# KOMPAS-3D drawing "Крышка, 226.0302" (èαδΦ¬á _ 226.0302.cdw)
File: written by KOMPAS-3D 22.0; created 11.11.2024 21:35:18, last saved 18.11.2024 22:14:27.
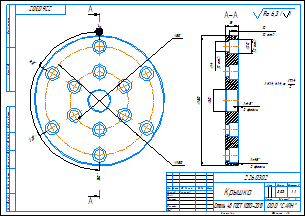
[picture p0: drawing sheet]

Sheet 1: A3, landscape

Document properties: Автор: aleksander.larionov.10@gmail.com; Знак неуказанной шероховатости: 4; Параметр неуказанной шероховатости: Ra 6,3; Полное имя файла: Крышка _ 226.0302.m3d; Масса: 3.032924

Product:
- Part/product: Крышка  | designation 226.0302
    Материал: Сталь 45 ГОСТ 1050-2013 (density 7810 kg/m3)
    Масса: 3.032924

Title block, sheet 1: Наименование: Крышка; designation: 226.0302; Материал: Сталь 45 ГОСТ 1050-2013; Масса: 3,03; Количество листов документа: 1; organisation: ООО "САЙН"; Форматы листов документа: A3; stored path: C:\Мои папки\Работа\Крышки, фланцы\226.0302\Крышка _ 226.0302.cdw; Разработал: Ларионов

Views: Вид 1, Сверху, Разрез А-А
Referenced files in C:\Мои папки\Работа\Крышки, фланцы\226.0302\: Крышка _ 226.0302.m3d
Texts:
  Ra 6,3
  Ra 6,3 ( )
Dimensions and other numbers on the sheet: 150; 80; 120; 180; 7; 226.0302; 30; 1; 2 фаски; 14; 12 отв.; 20; 12; 18; 1 H14, h14,    IT14 2 .; 1:1; 3,03; 226.0302 Крышка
